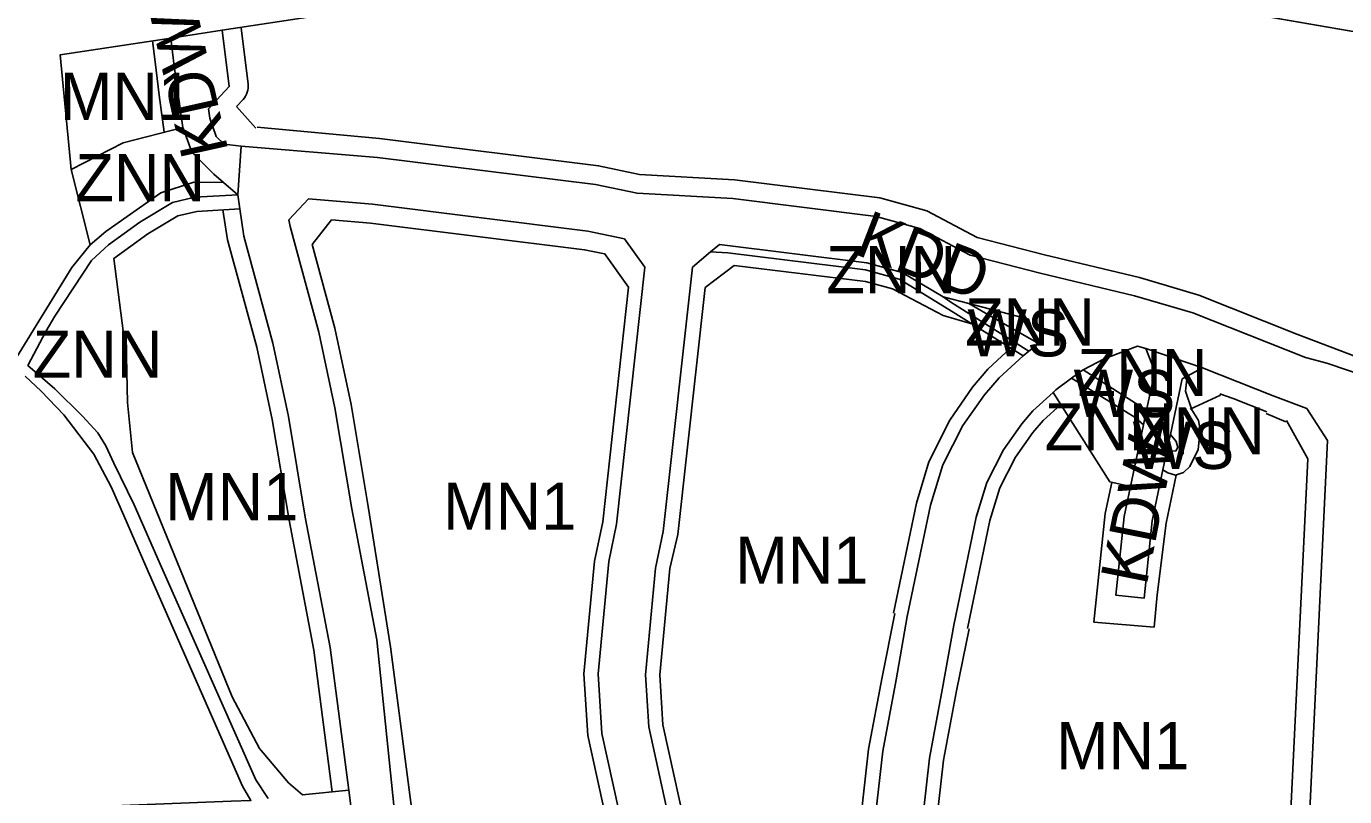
# Model space of a CAD drawing. Extents: x 7417187 to 7419415, y 5539178 to 5540826.
# Drawn here: x 7418455.5 to 7418734.7, y 5540070.1 to 5540233.3 of the extents above; entities that cross this region are included whole.
import ezdxf

# ---------------------------------------------------------------- set-up
doc = ezdxf.new("R2010")
doc.units = 0
for name, color, linetype in [('linie_rozgraniczajace', 7, 'Continuous'), ('linie_zabudowy_nieprzekraczalne', 7, 'Continuous'), ('oznaczenia_przeznaczen', 7, 'Continuous')]:
    doc.layers.add(name, color=color, linetype=linetype)

msp = doc.modelspace()

# ---------------------------------------------------------------- linework, layer by layer
at = {"layer": 'linie_rozgraniczajace'}
msp.add_line((7418819.13, 5540217.89), (7418625.49, 5540251.41), dxfattribs=at)
for points in [[(7418538.04, 5540238.68), (7418496.96, 5540232.44), (7418486.08, 5540230.79), (7418462.63, 5540227.22), (7418464.94, 5540202.93), (7418468.97, 5540186.98), (7418465.08, 5540182.22), (7418453.39, 5540163.14), (7418433.02, 5540170.19), (7418412.2, 5540176.64), (7418380.76, 5540186.27), (7418369.92, 5540190.23), (7418368.55, 5540190.85), (7418350.22, 5540206.58), (7418319.78, 5540232.65), (7418297.74, 5540250.66)], [(7418625.49, 5540251.41), (7418819.13, 5540217.89)], [(7418766.98, 5540149.72), (7418730.85, 5540161.92), (7418726.36, 5540163.1), (7418702.47, 5540172.59), (7418690.17, 5540176.18), (7418670.14, 5540180.96), (7418655.33, 5540184.82), (7418644.66, 5540190.47), (7418635.46, 5540193.03), (7418605.06, 5540196.79), (7418584.8, 5540197.94), (7418576, 5540199.79), (7418529.83, 5540205.53), (7418500.95, 5540207.91), (7418497.34, 5540208.29), (7418495.7, 5540209.92), (7418494.3, 5540213.82), (7418494.04, 5540215.8), (7418498.45, 5540220.53), (7418496.96, 5540232.44), (7418538.04, 5540238.68)], [(7418525.21, 5540060.34), (7418523.75, 5540071.5), (7418519.82, 5540101.72), (7418514.55, 5540129.29), (7418510.98, 5540150.63), (7418507.68, 5540166.17), (7418501.52, 5540188.81), (7418500.67, 5540194.63), (7418500.24, 5540197.59), (7418500.95, 5540207.91), (7418529.83, 5540205.53), (7418576, 5540199.79), (7418584.8, 5540197.94), (7418605.06, 5540196.79), (7418635.46, 5540193.03), (7418644.66, 5540190.47), (7418655.33, 5540184.82), (7418670.14, 5540180.96), (7418690.17, 5540176.18), (7418702.47, 5540172.59), (7418726.36, 5540163.1), (7418730.85, 5540161.92), (7418766.98, 5540149.72)], [(7418453.39, 5540163.14), (7418465.08, 5540182.22), (7418468.97, 5540186.98), (7418472.33, 5540189.8), (7418483.96, 5540198), (7418490.91, 5540200.27), (7418497.19, 5540200.23), (7418500.24, 5540197.59), (7418491.17, 5540197.06), (7418486.44, 5540195.95), (7418479.52, 5540191.81), (7418472.86, 5540186.98), (7418469.27, 5540183.68), (7418461.5, 5540171.89), (7418459.57, 5540168.65), (7418455.79, 5540161.42), (7418461.5, 5540156.5), (7418467.37, 5540150.73), (7418470.62, 5540147.16), (7418472.28, 5540144.39), (7418474.02, 5540140.78), (7418478.28, 5540131.9), (7418484.11, 5540118.73), (7418504.04, 5540073.69), (7418506.68, 5540069.75)], [(7418506.68, 5540069.75), (7418504.04, 5540073.69), (7418484.11, 5540118.73), (7418478.28, 5540131.9), (7418474.02, 5540140.78), (7418472.28, 5540144.39), (7418470.62, 5540147.16), (7418467.37, 5540150.73), (7418461.5, 5540156.5), (7418455.79, 5540161.42), (7418459.57, 5540168.65), (7418461.5, 5540171.89), (7418469.27, 5540183.68), (7418472.86, 5540186.98), (7418479.52, 5540191.81), (7418486.44, 5540195.95), (7418491.17, 5540197.06), (7418500.24, 5540197.59), (7418500.67, 5540194.63), (7418491.61, 5540194.08), (7418487.57, 5540193.14), (7418481.17, 5540189.3), (7418474.01, 5540184.11), (7418476.69, 5540163.3), (7418476.87, 5540153.58), (7418477.95, 5540143.04), (7418499.09, 5540091.22), (7418504.87, 5540080.34), (7418510.99, 5540073.06), (7418513.98, 5540070.52), (7418523.75, 5540071.5), (7418525.21, 5540060.34)], [(7418582.16, 5540061.73), (7418577.38, 5540083.46), (7418576.56, 5540096.09), (7418578.82, 5540119.95), (7418580.42, 5540127.84), (7418586.48, 5540182.28), (7418582.14, 5540188.28), (7418574.35, 5540189.92), (7418528.79, 5540195.58), (7418515.23, 5540196.73), (7418511.09, 5540192.28), (7418511.31, 5540190.91), (7418517.4, 5540168.52), (7418520.81, 5540152.49), (7418524.4, 5540131.05), (7418529.7, 5540103.31), (7418534.13, 5540060.05)], [(7418634.18, 5540056.26), (7418636.82, 5540079.76), (7418639.66, 5540094.86), (7418642.04, 5540108.29), (7418646.92, 5540131.83), (7418649.57, 5540140.41), (7418653.79, 5540148.71), (7418658.36, 5540155.24), (7418661.47, 5540158.85), (7418666.54, 5540163.46), (7418667.76, 5540164.46), (7418669.64, 5540165.87), (7418669.49, 5540166.29), (7418667.72, 5540171.26), (7418655.1, 5540174.55), (7418649.65, 5540175.97), (7418640.94, 5540181.12), (7418633.5, 5540183.19), (7418602.23, 5540187.07), (7418600.38, 5540185.5), (7418596.54, 5540182.26), (7418590.31, 5540126.29), (7418588.73, 5540118.48), (7418586.59, 5540095.94), (7418587.31, 5540084.87), (7418591.98, 5540063.61)], [(7418591.98, 5540063.61), (7418587.31, 5540084.87), (7418586.59, 5540095.94), (7418588.73, 5540118.48), (7418590.31, 5540126.29), (7418596.54, 5540182.26), (7418600.38, 5540185.5), (7418604.03, 5540185.33), (7418633.2, 5540181.72), (7418640.34, 5540179.73), (7418643.17, 5540178.06), (7418651.78, 5540172.7), (7418666.54, 5540163.46), (7418661.47, 5540158.85), (7418658.36, 5540155.24), (7418653.79, 5540148.71), (7418649.57, 5540140.41), (7418646.92, 5540131.83), (7418642.04, 5540108.29), (7418639.66, 5540094.86), (7418636.82, 5540079.76), (7418634.18, 5540056.26)], [(7418726.34, 5540048.02), (7418731.05, 5540145.52), (7418726.62, 5540152.3), (7418719.55, 5540154.99), (7418704.58, 5540160.97), (7418692.58, 5540165.06), (7418690.78, 5540165.52), (7418683.71, 5540162.88), (7418679.29, 5540160.53), (7418678.9, 5540160.32), (7418676.84, 5540158.77), (7418673.51, 5540156.28), (7418672.92, 5540155.74), (7418668.65, 5540151.86), (7418666.26, 5540149.09), (7418662.38, 5540143.56), (7418658.87, 5540136.64), (7418656.61, 5540129.33), (7418651.86, 5540106.4), (7418649.5, 5540093.07), (7418646.71, 5540078.27), (7418644.11, 5540055.05)], [(7418644.11, 5540055.05), (7418646.71, 5540078.27), (7418649.5, 5540093.07), (7418651.86, 5540106.4), (7418656.61, 5540129.33), (7418658.87, 5540136.64), (7418662.38, 5540143.56), (7418666.26, 5540149.09), (7418668.65, 5540151.86), (7418672.92, 5540155.74), (7418684.95, 5540136.76), (7418689.28, 5540135.84), (7418687.93, 5540129.46), (7418686.23, 5540112.76), (7418692.2, 5540112.16), (7418693.86, 5540128.53), (7418696.16, 5540139.34), (7418697.2, 5540138.73), (7418698.86, 5540138.19), (7418700.55, 5540138.78), (7418701.88, 5540140.04), (7418703.63, 5540143.64), (7418704.07, 5540147.79), (7418703.73, 5540149.76), (7418702.26, 5540152.03), (7418700.98, 5540156.03), (7418701.3, 5540159.17), (7418704.58, 5540160.97), (7418719.55, 5540154.99), (7418726.62, 5540152.3), (7418731.05, 5540145.52), (7418726.34, 5540048.02)], [(7418455.21, 5540159.2), (7418458.58, 5540156.01), (7418463.38, 5540150.96), (7418469.78, 5540142.69), (7418473.44, 5540135.76), (7418476.13, 5540129.63), (7418480.76, 5540118.92), (7418487.68, 5540103.18), (7418498.7, 5540078.12), (7418501.27, 5540072.34), (7418503.02, 5540069.31), (7418498.87, 5540069.14), (7418457.92, 5540067.55), (7418377.24, 5540064.07)], [(7418503.02, 5540069.31), (7418501.27, 5540072.34), (7418498.7, 5540078.12), (7418487.68, 5540103.18), (7418480.76, 5540118.92), (7418476.13, 5540129.63), (7418473.44, 5540135.76), (7418469.78, 5540142.69), (7418463.38, 5540150.96), (7418458.58, 5540156.01), (7418455.21, 5540159.2)]]:
    msp.add_lwpolyline(points, dxfattribs=at)
for points in [[(7418488.64, 5540211.88), (7418476, 5540208.63), (7418464.94, 5540202.93), (7418462.63, 5540227.22), (7418486.08, 5540230.79), (7418486.78, 5540224.85)], [(7418500.95, 5540207.91), (7418500.24, 5540197.59), (7418497.19, 5540200.23), (7418495.2, 5540201.95), (7418490.51, 5540206.62), (7418488.67, 5540211.68), (7418488.64, 5540211.88), (7418486.78, 5540224.85), (7418486.08, 5540230.79), (7418496.96, 5540232.44), (7418498.45, 5540220.53), (7418494.04, 5540215.8), (7418494.3, 5540213.82), (7418495.7, 5540209.92), (7418497.34, 5540208.29)], [(7418497.19, 5540200.23), (7418490.91, 5540200.27), (7418483.96, 5540198), (7418472.33, 5540189.8), (7418468.97, 5540186.98), (7418464.94, 5540202.93), (7418476, 5540208.63), (7418488.64, 5540211.88), (7418488.67, 5540211.68), (7418490.51, 5540206.62), (7418495.2, 5540201.95)], [(7418523.75, 5540071.5), (7418513.98, 5540070.52), (7418510.99, 5540073.06), (7418504.87, 5540080.34), (7418499.09, 5540091.22), (7418477.95, 5540143.04), (7418476.87, 5540153.58), (7418476.69, 5540163.3), (7418474.01, 5540184.11), (7418481.17, 5540189.3), (7418487.57, 5540193.14), (7418491.61, 5540194.08), (7418500.67, 5540194.63), (7418501.52, 5540188.81), (7418507.68, 5540166.17), (7418510.98, 5540150.63), (7418514.55, 5540129.29), (7418519.82, 5540101.72)], [(7418584.43, 5540047.42), (7418578.31, 5540051.98), (7418568.28, 5540058.76), (7418556.47, 5540059.02), (7418535.91, 5540059.15), (7418534.13, 5540060.05), (7418529.7, 5540103.31), (7418524.4, 5540131.05), (7418520.81, 5540152.49), (7418517.4, 5540168.52), (7418511.31, 5540190.91), (7418511.09, 5540192.28), (7418515.23, 5540196.73), (7418528.79, 5540195.58), (7418574.35, 5540189.92), (7418582.14, 5540188.28), (7418586.48, 5540182.28), (7418580.42, 5540127.84), (7418578.82, 5540119.95), (7418576.56, 5540096.09), (7418577.38, 5540083.46), (7418582.16, 5540061.73), (7418584.4, 5540048.01)], [(7418649.65, 5540175.97), (7418651.29, 5540174.87), (7418652.58, 5540173.98), (7418667.76, 5540164.46), (7418666.54, 5540163.46), (7418651.78, 5540172.7), (7418643.17, 5540178.06), (7418640.34, 5540179.73), (7418633.2, 5540181.72), (7418604.03, 5540185.33), (7418600.38, 5540185.5), (7418602.23, 5540187.07), (7418633.5, 5540183.19), (7418640.94, 5540181.12)], [(7418655.1, 5540174.55), (7418661.77, 5540170.68), (7418669.49, 5540166.29), (7418669.64, 5540165.87), (7418667.76, 5540164.46), (7418652.58, 5540173.98), (7418651.29, 5540174.87), (7418649.65, 5540175.97)], [(7418669.49, 5540166.29), (7418661.77, 5540170.68), (7418655.1, 5540174.55), (7418667.72, 5540171.26)], [(7418692.58, 5540165.06), (7418694.44, 5540160.17), (7418692.71, 5540151.99), (7418679.29, 5540160.53), (7418683.71, 5540162.88), (7418690.78, 5540165.52)], [(7418704.58, 5540160.97), (7418701.3, 5540159.17), (7418700.24, 5540158.59), (7418697.74, 5540146.83), (7418697.09, 5540143.74), (7418696.16, 5540139.34), (7418693.86, 5540128.53), (7418692.2, 5540112.16), (7418686.23, 5540112.76), (7418687.93, 5540129.46), (7418689.28, 5540135.84), (7418692.04, 5540148.85), (7418692.71, 5540151.99), (7418694.44, 5540160.17), (7418692.58, 5540165.06)], [(7418692.04, 5540148.85), (7418689.28, 5540135.84), (7418684.95, 5540136.76), (7418672.92, 5540155.74), (7418673.51, 5540156.28), (7418676.84, 5540158.77), (7418679.37, 5540157.2), (7418686.22, 5540152.93), (7418690.29, 5540150.42)], [(7418692.71, 5540151.99), (7418692.04, 5540148.85), (7418690.29, 5540150.42), (7418686.22, 5540152.93), (7418679.37, 5540157.2), (7418676.84, 5540158.77), (7418678.9, 5540160.32), (7418679.29, 5540160.53)], [(7418696.16, 5540139.34), (7418697.09, 5540143.74), (7418697.61, 5540143.19), (7418698.91, 5540143.34), (7418699.31, 5540144.09), (7418698.96, 5540145.37), (7418697.74, 5540146.83), (7418700.24, 5540158.59), (7418701.3, 5540159.17), (7418700.98, 5540156.03), (7418702.26, 5540152.03), (7418703.73, 5540149.76), (7418704.07, 5540147.79), (7418703.63, 5540143.64), (7418701.88, 5540140.04), (7418700.55, 5540138.78), (7418698.86, 5540138.19), (7418697.2, 5540138.73)], [(7418697.09, 5540143.74), (7418697.74, 5540146.83), (7418698.96, 5540145.37), (7418699.31, 5540144.09), (7418698.91, 5540143.34), (7418697.61, 5540143.19)]]:
    msp.add_lwpolyline(points, close=True, dxfattribs=at)
at = {"layer": 'linie_zabudowy_nieprzekraczalne'}
for points in [[(7418500.94, 5540232.94), (7418502.42, 5540221.03)], [(7418484.63, 5540210.85), (7418483.61, 5540218.73), (7418482.72, 5540225.75), (7418482.19, 5540230.2)], [(7418501.38, 5540217.81), (7418499.95, 5540216.27)], [(7418499.95, 5540216.27), (7418504.1, 5540211.69)], [(7418504.34, 5540211.91), (7418530.25, 5540209.51), (7418576.66, 5540203.74), (7418585.33, 5540201.91), (7418605.43, 5540200.78), (7418636.25, 5540196.96), (7418646.15, 5540194.21), (7418656.8, 5540188.57), (7418671.11, 5540184.85), (7418691.2, 5540180.05), (7418703.78, 5540176.37), (7418724.54, 5540168.08)], [(7418520.24, 5540071.14), (7418516.37, 5540101.17), (7418511.11, 5540128.67), (7418507.54, 5540149.97), (7418504.27, 5540165.35), (7418498.1, 5540188.08), (7418497.09, 5540194.42)], [(7418520.13, 5540192.3), (7418515.99, 5540187.06)], [(7418577.91, 5540185.08), (7418573.69, 5540185.97), (7418528.38, 5540191.61), (7418520.13, 5540192.3)], [(7418515.99, 5540187.06), (7418520.8, 5540169.35), (7418524.25, 5540153.15), (7418527.86, 5540131.58), (7418532.58, 5540101.82), (7418538.14, 5540059.1)], [(7418582.98, 5540178), (7418577.88, 5540185.13)], [(7418605.39, 5540182.65), (7418599.25, 5540177.98)], [(7418633.16, 5540179.21), (7418605.39, 5540182.65)], [(7418577.58, 5540128.3), (7418582.98, 5540178)], [(7418599.25, 5540177.98), (7418593.45, 5540125.67)], [(7418638.88, 5540177.69), (7418633.16, 5540179.21)], [(7418649.61, 5540172.01), (7418638.88, 5540177.69)], [(7418655.88, 5540170.17), (7418649.61, 5540172.01)], [(7418724.54, 5540168.08), (7418744.19, 5540160.59), (7418767.8, 5540152.62), (7418783.34, 5540149.05), (7418795.33, 5540146.96)], [(7418659.08, 5540160.67), (7418663.98, 5540165.16)], [(7418655.82, 5540156.84), (7418659.08, 5540160.67)], [(7418651.02, 5540149.88), (7418655.82, 5540156.84)], [(7418711.05, 5540154.43), (7418708.23, 5540155.45)], [(7418674.53, 5540153.15), (7418670.8, 5540149.76), (7418668.63, 5540147.25), (7418664.96, 5540142.01), (7418661.66, 5540135.52), (7418659.52, 5540128.59), (7418654.79, 5540105.75)], [(7418701.93, 5540152.17), (7418708.37, 5540155.16)], [(7418718.17, 5540151.59), (7418711.05, 5540154.43)], [(7418646.63, 5540141.06), (7418651.02, 5540149.88)], [(7418718.04, 5540151.29), (7418722.23, 5540149.48)], [(7418726.86, 5540141.66), (7418722.36, 5540149.78)], [(7418712.91, 5539973.19), (7418715.8, 5539992.79), (7418719.82, 5540013.27), (7418721.03, 5540023.54), (7418722.35, 5540048.22), (7418726.86, 5540141.66)], [(7418643.95, 5540132.3), (7418646.63, 5540141.06)], [(7418681.53, 5540107.07), (7418683.97, 5540130.08), (7418685.37, 5540136.68)], [(7418698.99, 5540138.24), (7418696.83, 5540128.07), (7418694.96, 5540112.88)], [(7418639.12, 5540108.97), (7418643.95, 5540132.3)], [(7418575.82, 5540119.97), (7418577.58, 5540128.3)], [(7418593.45, 5540125.67), (7418591.74, 5540118.46)], [(7418581.47, 5540047.35), (7418579.21, 5540061.17), (7418574.4, 5540083.04), (7418573.56, 5540096.13), (7418575.82, 5540119.97)], [(7418591.74, 5540118.46), (7418589.61, 5540095.89), (7418590.29, 5540085.29), (7418594.93, 5540064.18), (7418597.3, 5540049.69)], [(7418694.96, 5540112.88), (7418694.31, 5540106.02)], [(7418626.04, 5539985.54), (7418623.23, 5540009.71), (7418628.63, 5540037.16), (7418631.21, 5540056.62), (7418633.85, 5540080.2), (7418636.72, 5540095.41), (7418639.43, 5540108.91)], [(7418655.11, 5540105.69), (7418652.46, 5540092.53), (7418649.68, 5540077.83), (7418647.09, 5540054.68), (7418644.43, 5540034.56), (7418639.42, 5540009.08), (7418640.07, 5540003.48)], [(7418694.31, 5540106.02), (7418681.53, 5540107.07)]]:
    msp.add_lwpolyline(points, dxfattribs=at)
msp.add_arc((7418498.45, 5540220.55), 4.01, 316.9855, 6.8936, dxfattribs=at)

# ---------------------------------------------------------------- texts
at = {"layer": 'oznaczenia_przeznaczen'}
for s, rotation, p in [('KDW', 102.5625, (7418498.31, 5540206.84)), ('KDD', 338.955, (7418630.6, 5540185.13)), ('KDW', 78.7623, (7418692.7, 5540114.59))]:
    msp.add_text(s, height=10, rotation=rotation, dxfattribs=at).set_placement(p)
for s, p in [('MN1', (7418462.55, 5540213.45)), ('ZNN', (7418465.84, 5540196.21)), ('ZNN', (7418624.87, 5540176.72)), ('ZNN', (7418654.27, 5540165.64)), ('WS', (7418654.76, 5540163.35)), ('ZNN', (7418456.8, 5540158.83)), ('ZNN', (7418678.09, 5540154.96)), ('WS', (7418677.26, 5540150.52)), ('ZNN', (7418671.11, 5540143.45)), ('ZNN', (7418690.26, 5540142.61)), ('WS', (7418689.73, 5540139.52)), ('MN1', (7418484.85, 5540128.65)), ('MN1', (7418543.72, 5540126.63)), ('MN1', (7418605.59, 5540115.2)), ('MN1', (7418673.53, 5540075.93))]:
    msp.add_text(s, height=10, dxfattribs=at).set_placement(p)

doc.saveas('drawing.dxf')
